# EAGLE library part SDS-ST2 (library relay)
RELAY polarity, 2 x norm. open, NAiS
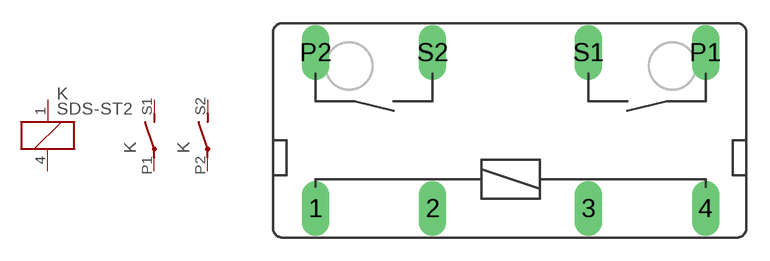
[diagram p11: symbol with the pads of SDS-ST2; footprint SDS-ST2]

Designator prefix K; gates 1=K 2=S 3=S

## SDS-ST2 (OC_FARNELL: unknown; OC_NEWARK: unknown)  [SDS-ST2]
1  1:1  pas
4  1:2  pas
P1  2:P  pas
P2  3:P  pas
S1  2:S  pas
S2  3:S  pas

## Footprint SDS-ST2 (pad centres in mm)
RELAY polarity, 2 x norm. open, NAiS
drill 1.194 long: 1 -12.7,-5.08; 2 -5.08,-5.08; 3 5.08,-5.08; 4 12.7,-5.08; P1 12.7,5.08; P2 -12.7,5.08; S1 5.08,5.08; S2 -5.08,5.08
